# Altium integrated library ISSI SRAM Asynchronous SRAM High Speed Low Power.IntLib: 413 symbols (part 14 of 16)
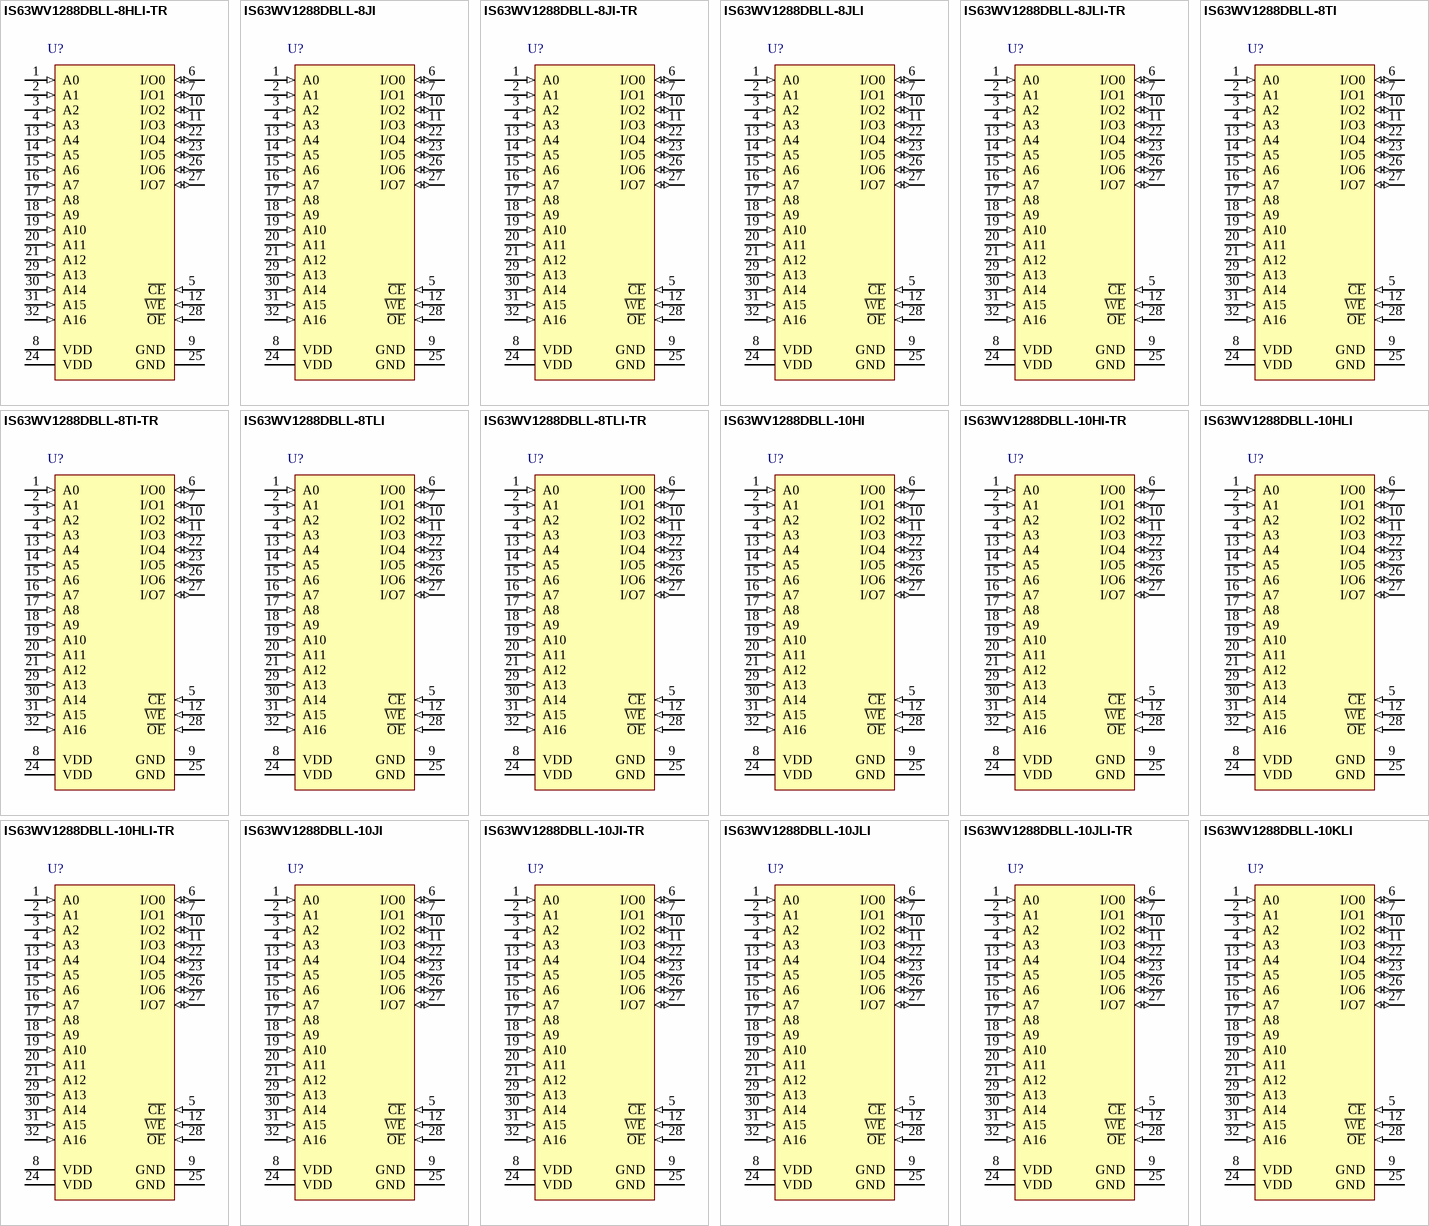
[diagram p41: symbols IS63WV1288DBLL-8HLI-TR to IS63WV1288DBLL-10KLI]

## IS63WV1288DBLL-8TI
designator U?
1 M High Speed CMOS SRAM, 128 K x 8, -40 to 85 degC, 32-Pin SOP (TSOP-2-32); Manufacturer: Integrated Silicon Solution Inc (ISSI); PartNumber: IS63WV1288DBLL-8TI; Organization: 128K x 8; Packing: Tray / Tube; Speed (ns): 8
footprint ISSI-TSOP-2-32_N (SOP, 32-Leads, Body 21.1x10.3mm, Pitch 1.27mm, IPC Medium Density)
pins: 1 A0 (in) "Address Inputs", 2 A1 (in) "Address Inputs", 3 A2 (in) "Address Inputs", 4 A3 (in) "Address Inputs", 5 ~{CE} (in) "Chip Enable Input", 6 I/O0 (io) "Bidirectional Ports", 7 I/O1 (io) "Bidirectional Ports", 8 VDD (power) "Power", 9 GND (power) "Ground", 10 I/O2 (io) "Bidirectional Ports", 11 I/O3 (io) "Bidirectional Ports", 12 ~{WE} (in) "Write Enable Input", 13 A4 (in) "Address Inputs", 14 A5 (in) "Address Inputs", 15 A6 (in) "Address Inputs", 16 A7 (in) "Address Inputs", 17 A8 (in) "Address Inputs", 18 A9 (in) "Address Inputs", 19 A10 (in) "Address Inputs", 20 A11 (in) "Address Inputs", 21 A12 (in) "Address Inputs", 22 I/O4 (io) "Bidirectional Ports", 23 I/O5 (io) "Bidirectional Ports", 24 VDD (power) "Power", 25 GND (power) "Ground", 26 I/O6 (io) "Bidirectional Ports", 27 I/O7 (io) "Bidirectional Ports", 28 ~{OE} (in) "Output Enable Input", 29 A13 (in) "Address Inputs", 30 A14 (in) "Address Inputs", 31 A15 (in) "Address Inputs", 32 A16 (in) "Address Inputs"

## IS63WV1288DBLL-8TI-TR
designator U?
1 M High Speed CMOS SRAM, 128 K x 8, -40 to 85 degC, 32-Pin SOP (TSOP-2-32); Manufacturer: Integrated Silicon Solution Inc (ISSI); PartNumber: IS63WV1288DBLL-8TI-TR; Organization: 128K x 8; Packing: Tape & Reel; Speed (ns): 8
footprint ISSI-TSOP-2-32_N (SOP, 32-Leads, Body 21.1x10.3mm, Pitch 1.27mm, IPC Medium Density)
pins: 1 A0 (in) "Address Inputs", 2 A1 (in) "Address Inputs", 3 A2 (in) "Address Inputs", 4 A3 (in) "Address Inputs", 5 ~{CE} (in) "Chip Enable Input", 6 I/O0 (io) "Bidirectional Ports", 7 I/O1 (io) "Bidirectional Ports", 8 VDD (power) "Power", 9 GND (power) "Ground", 10 I/O2 (io) "Bidirectional Ports", 11 I/O3 (io) "Bidirectional Ports", 12 ~{WE} (in) "Write Enable Input", 13 A4 (in) "Address Inputs", 14 A5 (in) "Address Inputs", 15 A6 (in) "Address Inputs", 16 A7 (in) "Address Inputs", 17 A8 (in) "Address Inputs", 18 A9 (in) "Address Inputs", 19 A10 (in) "Address Inputs", 20 A11 (in) "Address Inputs", 21 A12 (in) "Address Inputs", 22 I/O4 (io) "Bidirectional Ports", 23 I/O5 (io) "Bidirectional Ports", 24 VDD (power) "Power", 25 GND (power) "Ground", 26 I/O6 (io) "Bidirectional Ports", 27 I/O7 (io) "Bidirectional Ports", 28 ~{OE} (in) "Output Enable Input", 29 A13 (in) "Address Inputs", 30 A14 (in) "Address Inputs", 31 A15 (in) "Address Inputs", 32 A16 (in) "Address Inputs"

## IS63WV1288DBLL-8TLI
designator U?
1 M High Speed CMOS SRAM, 128 K x 8, -40 to 85 degC, 32-Pin SOP (TSOP-2-32), Pb-Free; Manufacturer: Integrated Silicon Solution Inc (ISSI); PartNumber: IS63WV1288DBLL-8TLI; Organization: 128K x 8; Packing: Tray / Tube; Speed (ns): 8
footprint ISSI-TSOP-2-32_N (SOP, 32-Leads, Body 21.1x10.3mm, Pitch 1.27mm, IPC Medium Density)
pins: 1 A0 (in) "Address Inputs", 2 A1 (in) "Address Inputs", 3 A2 (in) "Address Inputs", 4 A3 (in) "Address Inputs", 5 ~{CE} (in) "Chip Enable Input", 6 I/O0 (io) "Bidirectional Ports", 7 I/O1 (io) "Bidirectional Ports", 8 VDD (power) "Power", 9 GND (power) "Ground", 10 I/O2 (io) "Bidirectional Ports", 11 I/O3 (io) "Bidirectional Ports", 12 ~{WE} (in) "Write Enable Input", 13 A4 (in) "Address Inputs", 14 A5 (in) "Address Inputs", 15 A6 (in) "Address Inputs", 16 A7 (in) "Address Inputs", 17 A8 (in) "Address Inputs", 18 A9 (in) "Address Inputs", 19 A10 (in) "Address Inputs", 20 A11 (in) "Address Inputs", 21 A12 (in) "Address Inputs", 22 I/O4 (io) "Bidirectional Ports", 23 I/O5 (io) "Bidirectional Ports", 24 VDD (power) "Power", 25 GND (power) "Ground", 26 I/O6 (io) "Bidirectional Ports", 27 I/O7 (io) "Bidirectional Ports", 28 ~{OE} (in) "Output Enable Input", 29 A13 (in) "Address Inputs", 30 A14 (in) "Address Inputs", 31 A15 (in) "Address Inputs", 32 A16 (in) "Address Inputs"

## IS63WV1288DBLL-8TLI-TR
designator U?
1 M High Speed CMOS SRAM, 128 K x 8, -40 to 85 degC, 32-Pin SOP (TSOP-2-32), Pb-Free; Manufacturer: Integrated Silicon Solution Inc (ISSI); PartNumber: IS63WV1288DBLL-8TLI-TR; Organization: 128K x 8; Packing: Tape & Reel; Speed (ns): 8
footprint ISSI-TSOP-2-32_N (SOP, 32-Leads, Body 21.1x10.3mm, Pitch 1.27mm, IPC Medium Density)
pins: 1 A0 (in) "Address Inputs", 2 A1 (in) "Address Inputs", 3 A2 (in) "Address Inputs", 4 A3 (in) "Address Inputs", 5 ~{CE} (in) "Chip Enable Input", 6 I/O0 (io) "Bidirectional Ports", 7 I/O1 (io) "Bidirectional Ports", 8 VDD (power) "Power", 9 GND (power) "Ground", 10 I/O2 (io) "Bidirectional Ports", 11 I/O3 (io) "Bidirectional Ports", 12 ~{WE} (in) "Write Enable Input", 13 A4 (in) "Address Inputs", 14 A5 (in) "Address Inputs", 15 A6 (in) "Address Inputs", 16 A7 (in) "Address Inputs", 17 A8 (in) "Address Inputs", 18 A9 (in) "Address Inputs", 19 A10 (in) "Address Inputs", 20 A11 (in) "Address Inputs", 21 A12 (in) "Address Inputs", 22 I/O4 (io) "Bidirectional Ports", 23 I/O5 (io) "Bidirectional Ports", 24 VDD (power) "Power", 25 GND (power) "Ground", 26 I/O6 (io) "Bidirectional Ports", 27 I/O7 (io) "Bidirectional Ports", 28 ~{OE} (in) "Output Enable Input", 29 A13 (in) "Address Inputs", 30 A14 (in) "Address Inputs", 31 A15 (in) "Address Inputs", 32 A16 (in) "Address Inputs"

## IS63WV1288DBLL-10HI
designator U?
1 M High Speed CMOS SRAM, 128 K x 8, -40 to 85 degC, 32-Pin SOP (TSOP-1-32); Manufacturer: Integrated Silicon Solution Inc (ISSI); PartNumber: IS63WV1288DBLL-10HI; Organization: 128K x 8; Packing: Tray / Tube; Speed (ns): 10
footprint ISSI-TSOP-1-32-8000x13400DE_N (SOP, 32-Leads, Body 11.9x8.1mm, Pitch 0.5mm, IPC Medium Density)
pins: 1 A0 (in) "Address Input", 2 A1 (in) "Address Input", 3 A2 (in) "Address Input", 4 A3 (in) "Address Input", 5 ~{CE} (in) "Chip Enable Input", 6 I/O0 (io) "Bidirectional Port", 7 I/O1 (io) "Bidirectional Port", 8 VDD (power) "Power", 9 GND (power) "Ground", 10 I/O2 (io) "Bidirectional Port", 11 I/O3 (io) "Bidirectional Port", 12 ~{WE} (in) "Write Enable Input", 13 A4 (in) "Address Input", 14 A5 (in) "Address Input", 15 A6 (in) "Address Input", 16 A7 (in) "Address Input", 17 A8 (in) "Address Input", 18 A9 (in) "Address Input", 19 A10 (in) "Address Input", 20 A11 (in) "Address Input", 21 A12 (in) "Address Input", 22 I/O4 (io) "Bidirectional Port", 23 I/O5 (io) "Bidirectional Port", 24 VDD (power) "Power", 25 GND (power) "Ground", 26 I/O6 (io) "Bidirectional Port", 27 I/O7 (io) "Bidirectional Port", 28 ~{OE} (in) "Output Enable Input", 29 A13 (in) "Address Input", 30 A14 (in) "Address Input", 31 A15 (in) "Address Input", 32 A16 (in) "Address Input"

## IS63WV1288DBLL-10HI-TR
designator U?
1 M High Speed CMOS SRAM, 128 K x 8, -40 to 85 degC, 32-Pin SOP (TSOP-1-32); Manufacturer: Integrated Silicon Solution Inc (ISSI); PartNumber: IS63WV1288DBLL-10HI-TR; Organization: 128K x 8; Packing: Tape & Reel; Speed (ns): 10
footprint ISSI-TSOP-1-32-8000x13400DE_N (SOP, 32-Leads, Body 11.9x8.1mm, Pitch 0.5mm, IPC Medium Density)
pins: 1 A0 (in) "Address Input", 2 A1 (in) "Address Input", 3 A2 (in) "Address Input", 4 A3 (in) "Address Input", 5 ~{CE} (in) "Chip Enable Input", 6 I/O0 (io) "Bidirectional Port", 7 I/O1 (io) "Bidirectional Port", 8 VDD (power) "Power", 9 GND (power) "Ground", 10 I/O2 (io) "Bidirectional Port", 11 I/O3 (io) "Bidirectional Port", 12 ~{WE} (in) "Write Enable Input", 13 A4 (in) "Address Input", 14 A5 (in) "Address Input", 15 A6 (in) "Address Input", 16 A7 (in) "Address Input", 17 A8 (in) "Address Input", 18 A9 (in) "Address Input", 19 A10 (in) "Address Input", 20 A11 (in) "Address Input", 21 A12 (in) "Address Input", 22 I/O4 (io) "Bidirectional Port", 23 I/O5 (io) "Bidirectional Port", 24 VDD (power) "Power", 25 GND (power) "Ground", 26 I/O6 (io) "Bidirectional Port", 27 I/O7 (io) "Bidirectional Port", 28 ~{OE} (in) "Output Enable Input", 29 A13 (in) "Address Input", 30 A14 (in) "Address Input", 31 A15 (in) "Address Input", 32 A16 (in) "Address Input"

## IS63WV1288DBLL-10HLI
designator U?
1 M High Speed CMOS SRAM, 128 K x 8, -40 to 85 degC, 32-Pin SOP (TSOP-1-32), Pb-Free; Manufacturer: Integrated Silicon Solution Inc (ISSI); PartNumber: IS63WV1288DBLL-10HLI; Organization: 128K x 8; Packing: Tray / Tube; Speed (ns): 10
footprint ISSI-TSOP-1-32-8000x13400DE_N (SOP, 32-Leads, Body 11.9x8.1mm, Pitch 0.5mm, IPC Medium Density)
pins: 1 A0 (in) "Address Input", 2 A1 (in) "Address Input", 3 A2 (in) "Address Input", 4 A3 (in) "Address Input", 5 ~{CE} (in) "Chip Enable Input", 6 I/O0 (io) "Bidirectional Port", 7 I/O1 (io) "Bidirectional Port", 8 VDD (power) "Power", 9 GND (power) "Ground", 10 I/O2 (io) "Bidirectional Port", 11 I/O3 (io) "Bidirectional Port", 12 ~{WE} (in) "Write Enable Input", 13 A4 (in) "Address Input", 14 A5 (in) "Address Input", 15 A6 (in) "Address Input", 16 A7 (in) "Address Input", 17 A8 (in) "Address Input", 18 A9 (in) "Address Input", 19 A10 (in) "Address Input", 20 A11 (in) "Address Input", 21 A12 (in) "Address Input", 22 I/O4 (io) "Bidirectional Port", 23 I/O5 (io) "Bidirectional Port", 24 VDD (power) "Power", 25 GND (power) "Ground", 26 I/O6 (io) "Bidirectional Port", 27 I/O7 (io) "Bidirectional Port", 28 ~{OE} (in) "Output Enable Input", 29 A13 (in) "Address Input", 30 A14 (in) "Address Input", 31 A15 (in) "Address Input", 32 A16 (in) "Address Input"

## IS63WV1288DBLL-10HLI-TR
designator U?
1 M High Speed CMOS SRAM, 128 K x 8, -40 to 85 degC, 32-Pin SOP (TSOP-1-32), Pb-Free; Manufacturer: Integrated Silicon Solution Inc (ISSI); PartNumber: IS63WV1288DBLL-10HLI-TR; Organization: 128K x 8; Packing: Tape & Reel; Speed (ns): 10
footprint ISSI-TSOP-1-32-8000x13400DE_N (SOP, 32-Leads, Body 11.9x8.1mm, Pitch 0.5mm, IPC Medium Density)
pins: 1 A0 (in) "Address Input", 2 A1 (in) "Address Input", 3 A2 (in) "Address Input", 4 A3 (in) "Address Input", 5 ~{CE} (in) "Chip Enable Input", 6 I/O0 (io) "Bidirectional Port", 7 I/O1 (io) "Bidirectional Port", 8 VDD (power) "Power", 9 GND (power) "Ground", 10 I/O2 (io) "Bidirectional Port", 11 I/O3 (io) "Bidirectional Port", 12 ~{WE} (in) "Write Enable Input", 13 A4 (in) "Address Input", 14 A5 (in) "Address Input", 15 A6 (in) "Address Input", 16 A7 (in) "Address Input", 17 A8 (in) "Address Input", 18 A9 (in) "Address Input", 19 A10 (in) "Address Input", 20 A11 (in) "Address Input", 21 A12 (in) "Address Input", 22 I/O4 (io) "Bidirectional Port", 23 I/O5 (io) "Bidirectional Port", 24 VDD (power) "Power", 25 GND (power) "Ground", 26 I/O6 (io) "Bidirectional Port", 27 I/O7 (io) "Bidirectional Port", 28 ~{OE} (in) "Output Enable Input", 29 A13 (in) "Address Input", 30 A14 (in) "Address Input", 31 A15 (in) "Address Input", 32 A16 (in) "Address Input"

## IS63WV1288DBLL-10JI
designator U?
1 M High Speed CMOS SRAM, 128 K x 8, -40 to 85 degC, 32-Pin SOJ (SOJ-32_A); Manufacturer: Integrated Silicon Solution Inc (ISSI); PartNumber: IS63WV1288DBLL-10JI; Organization: 128K x 8; Packing: Tray / Tube; Speed (ns): 10
footprint ISSI-SOJ-32_A_N (SOJ, 32-Leads, Body 21.09x7.75mm, Pitch 1.27mm, IPC Medium Density)
pins: 1 A0 (in) "Address Input", 2 A1 (in) "Address Input", 3 A2 (in) "Address Input", 4 A3 (in) "Address Input", 5 ~{CE} (in) "Chip Enable Input", 6 I/O0 (io) "Bidirectional Port", 7 I/O1 (io) "Bidirectional Port", 8 VDD (power) "Power", 9 GND (power) "Ground", 10 I/O2 (io) "Bidirectional Port", 11 I/O3 (io) "Bidirectional Port", 12 ~{WE} (in) "Write Enable Input", 13 A4 (in) "Address Input", 14 A5 (in) "Address Input", 15 A6 (in) "Address Input", 16 A7 (in) "Address Input", 17 A8 (in) "Address Input", 18 A9 (in) "Address Input", 19 A10 (in) "Address Input", 20 A11 (in) "Address Input", 21 A12 (in) "Address Input", 22 I/O4 (io) "Bidirectional Port", 23 I/O5 (io) "Bidirectional Port", 24 VDD (power) "Power", 25 GND (power) "Ground", 26 I/O6 (io) "Bidirectional Port", 27 I/O7 (io) "Bidirectional Port", 28 ~{OE} (in) "Output Enable Input", 29 A13 (in) "Address Input", 30 A14 (in) "Address Input", 31 A15 (in) "Address Input", 32 A16 (in) "Address Input"

## IS63WV1288DBLL-10JI-TR
designator U?
1 M High Speed CMOS SRAM, 128 K x 8, -40 to 85 degC, 32-Pin SOJ (SOJ-32_A); Manufacturer: Integrated Silicon Solution Inc (ISSI); PartNumber: IS63WV1288DBLL-10JI-TR; Organization: 128K x 8; Packing: Tape & Reel; Speed (ns): 10
footprint ISSI-SOJ-32_A_N (SOJ, 32-Leads, Body 21.09x7.75mm, Pitch 1.27mm, IPC Medium Density)
pins: 1 A0 (in) "Address Input", 2 A1 (in) "Address Input", 3 A2 (in) "Address Input", 4 A3 (in) "Address Input", 5 ~{CE} (in) "Chip Enable Input", 6 I/O0 (io) "Bidirectional Port", 7 I/O1 (io) "Bidirectional Port", 8 VDD (power) "Power", 9 GND (power) "Ground", 10 I/O2 (io) "Bidirectional Port", 11 I/O3 (io) "Bidirectional Port", 12 ~{WE} (in) "Write Enable Input", 13 A4 (in) "Address Input", 14 A5 (in) "Address Input", 15 A6 (in) "Address Input", 16 A7 (in) "Address Input", 17 A8 (in) "Address Input", 18 A9 (in) "Address Input", 19 A10 (in) "Address Input", 20 A11 (in) "Address Input", 21 A12 (in) "Address Input", 22 I/O4 (io) "Bidirectional Port", 23 I/O5 (io) "Bidirectional Port", 24 VDD (power) "Power", 25 GND (power) "Ground", 26 I/O6 (io) "Bidirectional Port", 27 I/O7 (io) "Bidirectional Port", 28 ~{OE} (in) "Output Enable Input", 29 A13 (in) "Address Input", 30 A14 (in) "Address Input", 31 A15 (in) "Address Input", 32 A16 (in) "Address Input"

## IS63WV1288DBLL-10JLI
designator U?
1 M High Speed CMOS SRAM, 128 K x 8, -40 to 85 degC, 32-Pin SOJ (SOJ-32_A), Pb-Free; Manufacturer: Integrated Silicon Solution Inc (ISSI); PartNumber: IS63WV1288DBLL-10JLI; Organization: 128K x 8; Packing: Tray / Tube; Speed (ns): 10
footprint ISSI-SOJ-32_A_N (SOJ, 32-Leads, Body 21.09x7.75mm, Pitch 1.27mm, IPC Medium Density)
pins: 1 A0 (in) "Address Input", 2 A1 (in) "Address Input", 3 A2 (in) "Address Input", 4 A3 (in) "Address Input", 5 ~{CE} (in) "Chip Enable Input", 6 I/O0 (io) "Bidirectional Port", 7 I/O1 (io) "Bidirectional Port", 8 VDD (power) "Power", 9 GND (power) "Ground", 10 I/O2 (io) "Bidirectional Port", 11 I/O3 (io) "Bidirectional Port", 12 ~{WE} (in) "Write Enable Input", 13 A4 (in) "Address Input", 14 A5 (in) "Address Input", 15 A6 (in) "Address Input", 16 A7 (in) "Address Input", 17 A8 (in) "Address Input", 18 A9 (in) "Address Input", 19 A10 (in) "Address Input", 20 A11 (in) "Address Input", 21 A12 (in) "Address Input", 22 I/O4 (io) "Bidirectional Port", 23 I/O5 (io) "Bidirectional Port", 24 VDD (power) "Power", 25 GND (power) "Ground", 26 I/O6 (io) "Bidirectional Port", 27 I/O7 (io) "Bidirectional Port", 28 ~{OE} (in) "Output Enable Input", 29 A13 (in) "Address Input", 30 A14 (in) "Address Input", 31 A15 (in) "Address Input", 32 A16 (in) "Address Input"

## IS63WV1288DBLL-10JLI-TR
designator U?
1 M High Speed CMOS SRAM, 128 K x 8, -40 to 85 degC, 32-Pin SOJ (SOJ-32_A), Pb-Free; Manufacturer: Integrated Silicon Solution Inc (ISSI); PartNumber: IS63WV1288DBLL-10JLI-TR; Organization: 128K x 8; Packing: Tape & Reel; Speed (ns): 10
footprint ISSI-SOJ-32_A_N (SOJ, 32-Leads, Body 21.09x7.75mm, Pitch 1.27mm, IPC Medium Density)
pins: 1 A0 (in) "Address Input", 2 A1 (in) "Address Input", 3 A2 (in) "Address Input", 4 A3 (in) "Address Input", 5 ~{CE} (in) "Chip Enable Input", 6 I/O0 (io) "Bidirectional Port", 7 I/O1 (io) "Bidirectional Port", 8 VDD (power) "Power", 9 GND (power) "Ground", 10 I/O2 (io) "Bidirectional Port", 11 I/O3 (io) "Bidirectional Port", 12 ~{WE} (in) "Write Enable Input", 13 A4 (in) "Address Input", 14 A5 (in) "Address Input", 15 A6 (in) "Address Input", 16 A7 (in) "Address Input", 17 A8 (in) "Address Input", 18 A9 (in) "Address Input", 19 A10 (in) "Address Input", 20 A11 (in) "Address Input", 21 A12 (in) "Address Input", 22 I/O4 (io) "Bidirectional Port", 23 I/O5 (io) "Bidirectional Port", 24 VDD (power) "Power", 25 GND (power) "Ground", 26 I/O6 (io) "Bidirectional Port", 27 I/O7 (io) "Bidirectional Port", 28 ~{OE} (in) "Output Enable Input", 29 A13 (in) "Address Input", 30 A14 (in) "Address Input", 31 A15 (in) "Address Input", 32 A16 (in) "Address Input"

## IS63WV1288DBLL-10KLI
designator U?
1 M High Speed CMOS SRAM, 128 K x 8, -40 to 85 degC, 32-Pin SOJ (SOJ-32_B), Pb-Free; Manufacturer: Integrated Silicon Solution Inc (ISSI); PartNumber: IS63WV1288DBLL-10KLI; Organization: 128K x 8; Packing: Tray / Tube; Speed (ns): 10
footprint ISSI-SOJ-32_B_N (SOJ, 32-Leads, Body 21.08x10.29mm, Pitch 1.27mm, IPC Medium Density)
pins: 1 A0 (in) "Address Input", 2 A1 (in) "Address Input", 3 A2 (in) "Address Input", 4 A3 (in) "Address Input", 5 ~{CE} (in) "Chip Enable Input", 6 I/O0 (io) "Bidirectional Port", 7 I/O1 (io) "Bidirectional Port", 8 VDD (power) "Power", 9 GND (power) "Ground", 10 I/O2 (io) "Bidirectional Port", 11 I/O3 (io) "Bidirectional Port", 12 ~{WE} (in) "Write Enable Input", 13 A4 (in) "Address Input", 14 A5 (in) "Address Input", 15 A6 (in) "Address Input", 16 A7 (in) "Address Input", 17 A8 (in) "Address Input", 18 A9 (in) "Address Input", 19 A10 (in) "Address Input", 20 A11 (in) "Address Input", 21 A12 (in) "Address Input", 22 I/O4 (io) "Bidirectional Port", 23 I/O5 (io) "Bidirectional Port", 24 VDD (power) "Power", 25 GND (power) "Ground", 26 I/O6 (io) "Bidirectional Port", 27 I/O7 (io) "Bidirectional Port", 28 ~{OE} (in) "Output Enable Input", 29 A13 (in) "Address Input", 30 A14 (in) "Address Input", 31 A15 (in) "Address Input", 32 A16 (in) "Address Input"

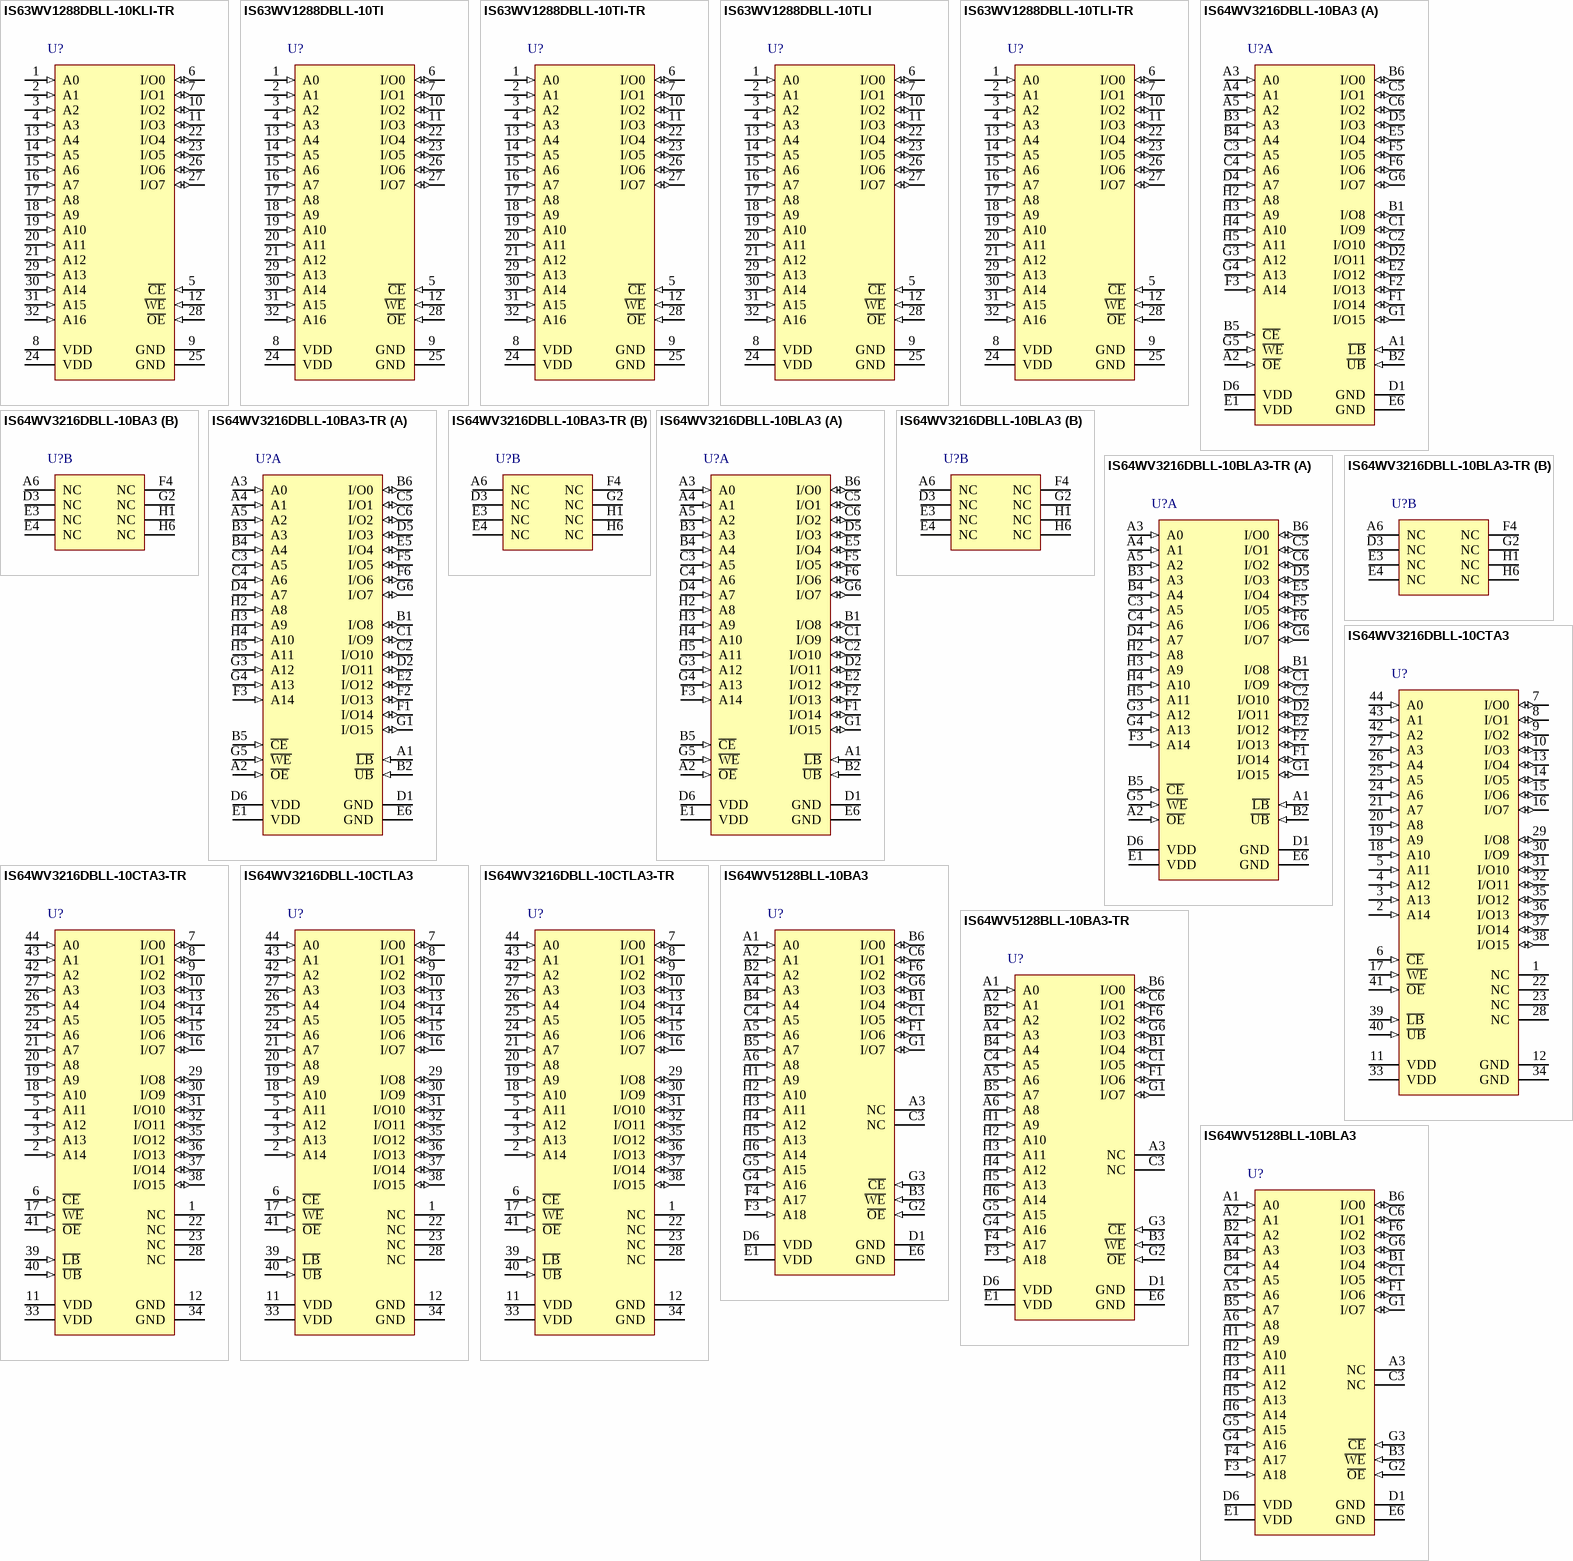
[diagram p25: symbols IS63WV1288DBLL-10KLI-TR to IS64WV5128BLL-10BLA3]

## IS63WV1288DBLL-10KLI-TR
designator U?
1 M High Speed CMOS SRAM, 128 K x 8, -40 to 85 degC, 32-Pin SOJ (SOJ-32_B), Pb-Free; Manufacturer: Integrated Silicon Solution Inc (ISSI); PartNumber: IS63WV1288DBLL-10KLI-TR; Organization: 128K x 8; Packing: Tape & Reel; Speed (ns): 10
footprint ISSI-SOJ-32_B_N (SOJ, 32-Leads, Body 21.08x10.29mm, Pitch 1.27mm, IPC Medium Density)
pins: 1 A0 (in) "Address Input", 2 A1 (in) "Address Input", 3 A2 (in) "Address Input", 4 A3 (in) "Address Input", 5 ~{CE} (in) "Chip Enable Input", 6 I/O0 (io) "Bidirectional Port", 7 I/O1 (io) "Bidirectional Port", 8 VDD (power) "Power", 9 GND (power) "Ground", 10 I/O2 (io) "Bidirectional Port", 11 I/O3 (io) "Bidirectional Port", 12 ~{WE} (in) "Write Enable Input", 13 A4 (in) "Address Input", 14 A5 (in) "Address Input", 15 A6 (in) "Address Input", 16 A7 (in) "Address Input", 17 A8 (in) "Address Input", 18 A9 (in) "Address Input", 19 A10 (in) "Address Input", 20 A11 (in) "Address Input", 21 A12 (in) "Address Input", 22 I/O4 (io) "Bidirectional Port", 23 I/O5 (io) "Bidirectional Port", 24 VDD (power) "Power", 25 GND (power) "Ground", 26 I/O6 (io) "Bidirectional Port", 27 I/O7 (io) "Bidirectional Port", 28 ~{OE} (in) "Output Enable Input", 29 A13 (in) "Address Input", 30 A14 (in) "Address Input", 31 A15 (in) "Address Input", 32 A16 (in) "Address Input"

## IS63WV1288DBLL-10TI
designator U?
1 M High Speed CMOS SRAM, 128 K x 8, -40 to 85 degC, 32-Pin SOP (TSOP-2-32); Manufacturer: Integrated Silicon Solution Inc (ISSI); PartNumber: IS63WV1288DBLL-10TI; Organization: 128K x 8; Packing: Tray / Tube; Speed (ns): 10
footprint ISSI-TSOP-2-32_N (SOP, 32-Leads, Body 21.1x10.3mm, Pitch 1.27mm, IPC Medium Density)
pins: 1 A0 (in) "Address Inputs", 2 A1 (in) "Address Inputs", 3 A2 (in) "Address Inputs", 4 A3 (in) "Address Inputs", 5 ~{CE} (in) "Chip Enable Input", 6 I/O0 (io) "Bidirectional Ports", 7 I/O1 (io) "Bidirectional Ports", 8 VDD (power) "Power", 9 GND (power) "Ground", 10 I/O2 (io) "Bidirectional Ports", 11 I/O3 (io) "Bidirectional Ports", 12 ~{WE} (in) "Write Enable Input", 13 A4 (in) "Address Inputs", 14 A5 (in) "Address Inputs", 15 A6 (in) "Address Inputs", 16 A7 (in) "Address Inputs", 17 A8 (in) "Address Inputs", 18 A9 (in) "Address Inputs", 19 A10 (in) "Address Inputs", 20 A11 (in) "Address Inputs", 21 A12 (in) "Address Inputs", 22 I/O4 (io) "Bidirectional Ports", 23 I/O5 (io) "Bidirectional Ports", 24 VDD (power) "Power", 25 GND (power) "Ground", 26 I/O6 (io) "Bidirectional Ports", 27 I/O7 (io) "Bidirectional Ports", 28 ~{OE} (in) "Output Enable Input", 29 A13 (in) "Address Inputs", 30 A14 (in) "Address Inputs", 31 A15 (in) "Address Inputs", 32 A16 (in) "Address Inputs"

## IS63WV1288DBLL-10TI-TR
designator U?
1 M High Speed CMOS SRAM, 128 K x 8, -40 to 85 degC, 32-Pin SOP (TSOP-2-32); Manufacturer: Integrated Silicon Solution Inc (ISSI); PartNumber: IS63WV1288DBLL-10TI-TR; Organization: 128K x 8; Packing: Tape & Reel; Speed (ns): 10
footprint ISSI-TSOP-2-32_N (SOP, 32-Leads, Body 21.1x10.3mm, Pitch 1.27mm, IPC Medium Density)
pins: 1 A0 (in) "Address Inputs", 2 A1 (in) "Address Inputs", 3 A2 (in) "Address Inputs", 4 A3 (in) "Address Inputs", 5 ~{CE} (in) "Chip Enable Input", 6 I/O0 (io) "Bidirectional Ports", 7 I/O1 (io) "Bidirectional Ports", 8 VDD (power) "Power", 9 GND (power) "Ground", 10 I/O2 (io) "Bidirectional Ports", 11 I/O3 (io) "Bidirectional Ports", 12 ~{WE} (in) "Write Enable Input", 13 A4 (in) "Address Inputs", 14 A5 (in) "Address Inputs", 15 A6 (in) "Address Inputs", 16 A7 (in) "Address Inputs", 17 A8 (in) "Address Inputs", 18 A9 (in) "Address Inputs", 19 A10 (in) "Address Inputs", 20 A11 (in) "Address Inputs", 21 A12 (in) "Address Inputs", 22 I/O4 (io) "Bidirectional Ports", 23 I/O5 (io) "Bidirectional Ports", 24 VDD (power) "Power", 25 GND (power) "Ground", 26 I/O6 (io) "Bidirectional Ports", 27 I/O7 (io) "Bidirectional Ports", 28 ~{OE} (in) "Output Enable Input", 29 A13 (in) "Address Inputs", 30 A14 (in) "Address Inputs", 31 A15 (in) "Address Inputs", 32 A16 (in) "Address Inputs"

## IS63WV1288DBLL-10TLI
designator U?
1 M High Speed CMOS SRAM, 128 K x 8, -40 to 85 degC, 32-Pin SOP (TSOP-2-32), Pb-Free; Manufacturer: Integrated Silicon Solution Inc (ISSI); PartNumber: IS63WV1288DBLL-10TLI; Organization: 128K x 8; Packing: Tray / Tube; Speed (ns): 10
footprint ISSI-TSOP-2-32_N (SOP, 32-Leads, Body 21.1x10.3mm, Pitch 1.27mm, IPC Medium Density)
pins: 1 A0 (in) "Address Inputs", 2 A1 (in) "Address Inputs", 3 A2 (in) "Address Inputs", 4 A3 (in) "Address Inputs", 5 ~{CE} (in) "Chip Enable Input", 6 I/O0 (io) "Bidirectional Ports", 7 I/O1 (io) "Bidirectional Ports", 8 VDD (power) "Power", 9 GND (power) "Ground", 10 I/O2 (io) "Bidirectional Ports", 11 I/O3 (io) "Bidirectional Ports", 12 ~{WE} (in) "Write Enable Input", 13 A4 (in) "Address Inputs", 14 A5 (in) "Address Inputs", 15 A6 (in) "Address Inputs", 16 A7 (in) "Address Inputs", 17 A8 (in) "Address Inputs", 18 A9 (in) "Address Inputs", 19 A10 (in) "Address Inputs", 20 A11 (in) "Address Inputs", 21 A12 (in) "Address Inputs", 22 I/O4 (io) "Bidirectional Ports", 23 I/O5 (io) "Bidirectional Ports", 24 VDD (power) "Power", 25 GND (power) "Ground", 26 I/O6 (io) "Bidirectional Ports", 27 I/O7 (io) "Bidirectional Ports", 28 ~{OE} (in) "Output Enable Input", 29 A13 (in) "Address Inputs", 30 A14 (in) "Address Inputs", 31 A15 (in) "Address Inputs", 32 A16 (in) "Address Inputs"

## IS63WV1288DBLL-10TLI-TR
designator U?
1 M High Speed CMOS SRAM, 128 K x 8, -40 to 85 degC, 32-Pin SOP (TSOP-2-32), Pb-Free; Manufacturer: Integrated Silicon Solution Inc (ISSI); PartNumber: IS63WV1288DBLL-10TLI-TR; Organization: 128K x 8; Packing: Tape & Reel; Speed (ns): 10
footprint ISSI-TSOP-2-32_N (SOP, 32-Leads, Body 21.1x10.3mm, Pitch 1.27mm, IPC Medium Density)
pins: 1 A0 (in) "Address Inputs", 2 A1 (in) "Address Inputs", 3 A2 (in) "Address Inputs", 4 A3 (in) "Address Inputs", 5 ~{CE} (in) "Chip Enable Input", 6 I/O0 (io) "Bidirectional Ports", 7 I/O1 (io) "Bidirectional Ports", 8 VDD (power) "Power", 9 GND (power) "Ground", 10 I/O2 (io) "Bidirectional Ports", 11 I/O3 (io) "Bidirectional Ports", 12 ~{WE} (in) "Write Enable Input", 13 A4 (in) "Address Inputs", 14 A5 (in) "Address Inputs", 15 A6 (in) "Address Inputs", 16 A7 (in) "Address Inputs", 17 A8 (in) "Address Inputs", 18 A9 (in) "Address Inputs", 19 A10 (in) "Address Inputs", 20 A11 (in) "Address Inputs", 21 A12 (in) "Address Inputs", 22 I/O4 (io) "Bidirectional Ports", 23 I/O5 (io) "Bidirectional Ports", 24 VDD (power) "Power", 25 GND (power) "Ground", 26 I/O6 (io) "Bidirectional Ports", 27 I/O7 (io) "Bidirectional Ports", 28 ~{OE} (in) "Output Enable Input", 29 A13 (in) "Address Inputs", 30 A14 (in) "Address Inputs", 31 A15 (in) "Address Inputs", 32 A16 (in) "Address Inputs"

## IS64WV3216DBLL-10BA3
designator U?
512 K High Speed Asynchronous CMOS SRAM, 32 K x 16, -40 to 125 degC, 48-Pin BGA (TF-BGA-48); Manufacturer: Integrated Silicon Solution Inc (ISSI); PartNumber: IS64WV3216DBLL-10BA3; Density: 512K; Organization: 32K x 16; Packing: Tray / Tube; Speed (ns): 10
footprint ISSI-TF-BGA-48-6000X8000DE (BGA, 48-Balls, Body 8x6mm, Pitch 0.75mm)
part A pins: A1 ~{LB} (in) "Lower-byte Control(I/O0-I/O7)", A2 ~{OE} (in) "Output Enable Input", A3 A0 (in) "Address Input", A4 A1 (in) "Address Input", A5 A2 (in) "Address Input", B1 I/O8 (io) "Data Input/Output", B2 ~{UB} (in) "Upper-byte Control(I/O8-I/O15)", B3 A3 (in) "Address Input", B4 A4 (in) "Address Input", B5 ~{CE} (in) "Chip Enable Input", B6 I/O0 (io) "Data Input/Output", C1 I/O9 (io) "Data Input/Output", C2 I/O10 (io) "Data Input/Output", C3 A5 (in) "Address Input", C4 A6 (in) "Address Input", C5 I/O1 (io) "Data Input/Output", C6 I/O2 (io) "Data Input/Output", D1 GND (power) "Ground", D2 I/O11 (io) "Data Input/Output", D4 A7 (in) "Address Input", D5 I/O3 (io) "Data Input/Output", D6 VDD (power) "Power", E1 VDD (power) "Power", E2 I/O12 (io) "Data Input/Output", E5 I/O4 (io) "Data Input/Output", E6 GND (power) "Ground", F1 I/O14 (io) "Data Input/Output", F2 I/O13 (io) "Data Input/Output", F3 A14 (in) "Address Input", F5 I/O5 (io) "Data Input/Output", F6 I/O6 (io) "Data Input/Output", G1 I/O15 (io) "Data Input/Output", G3 A12 (in) "Address Input", G4 A13 (in) "Address Input", G5 ~{WE} (in) "Write Enable Input", G6 I/O7 (io) "Data Input/Output", H2 A8 (in) "Address Input", H3 A9 (in) "Address Input", H4 A10 (in) "Address Input", H5 A11 (in) "Address Input"
part B pins: A6 NC "No Connection", D3 NC "No Connection", E3 NC "No Connection", E4 NC "No Connection", F4 NC "No Connection", G2 NC "No Connection", H1 NC "No Connection", H6 NC "No Connection"

## IS64WV3216DBLL-10BA3-TR
designator U?
512 K High Speed Asynchronous CMOS SRAM, 32 K x 16, -40 to 125 degC, 48-Pin BGA (TF-BGA-48); Manufacturer: Integrated Silicon Solution Inc (ISSI); PartNumber: IS64WV3216DBLL-10BA3-TR; Density: 512K; Organization: 32K x 16; Packing: Tape & Reel; Speed (ns): 10
footprint ISSI-TF-BGA-48-6000X8000DE (BGA, 48-Balls, Body 8x6mm, Pitch 0.75mm)
part A pins: A1 ~{LB} (in) "Lower-byte Control(I/O0-I/O7)", A2 ~{OE} (in) "Output Enable Input", A3 A0 (in) "Address Input", A4 A1 (in) "Address Input", A5 A2 (in) "Address Input", B1 I/O8 (io) "Data Input/Output", B2 ~{UB} (in) "Upper-byte Control(I/O8-I/O15)", B3 A3 (in) "Address Input", B4 A4 (in) "Address Input", B5 ~{CE} (in) "Chip Enable Input", B6 I/O0 (io) "Data Input/Output", C1 I/O9 (io) "Data Input/Output", C2 I/O10 (io) "Data Input/Output", C3 A5 (in) "Address Input", C4 A6 (in) "Address Input", C5 I/O1 (io) "Data Input/Output", C6 I/O2 (io) "Data Input/Output", D1 GND (power) "Ground", D2 I/O11 (io) "Data Input/Output", D4 A7 (in) "Address Input", D5 I/O3 (io) "Data Input/Output", D6 VDD (power) "Power", E1 VDD (power) "Power", E2 I/O12 (io) "Data Input/Output", E5 I/O4 (io) "Data Input/Output", E6 GND (power) "Ground", F1 I/O14 (io) "Data Input/Output", F2 I/O13 (io) "Data Input/Output", F3 A14 (in) "Address Input", F5 I/O5 (io) "Data Input/Output", F6 I/O6 (io) "Data Input/Output", G1 I/O15 (io) "Data Input/Output", G3 A12 (in) "Address Input", G4 A13 (in) "Address Input", G5 ~{WE} (in) "Write Enable Input", G6 I/O7 (io) "Data Input/Output", H2 A8 (in) "Address Input", H3 A9 (in) "Address Input", H4 A10 (in) "Address Input", H5 A11 (in) "Address Input"
part B pins: A6 NC "No Connection", D3 NC "No Connection", E3 NC "No Connection", E4 NC "No Connection", F4 NC "No Connection", G2 NC "No Connection", H1 NC "No Connection", H6 NC "No Connection"

## IS64WV3216DBLL-10BLA3
designator U?
512 K High Speed Asynchronous CMOS SRAM, 32 K x 16, -40 to 125 degC, 48-Pin BGA (TF-BGA-48), Pb-Free; Manufacturer: Integrated Silicon Solution Inc (ISSI); PartNumber: IS64WV3216DBLL-10BLA3; Density: 512K; Organization: 32K x 16; Packing: Tray / Tube; Speed (ns): 10
footprint ISSI-TF-BGA-48-6000X8000DE (BGA, 48-Balls, Body 8x6mm, Pitch 0.75mm)
part A pins: A1 ~{LB} (in) "Lower-byte Control(I/O0-I/O7)", A2 ~{OE} (in) "Output Enable Input", A3 A0 (in) "Address Input", A4 A1 (in) "Address Input", A5 A2 (in) "Address Input", B1 I/O8 (io) "Data Input/Output", B2 ~{UB} (in) "Upper-byte Control(I/O8-I/O15)", B3 A3 (in) "Address Input", B4 A4 (in) "Address Input", B5 ~{CE} (in) "Chip Enable Input", B6 I/O0 (io) "Data Input/Output", C1 I/O9 (io) "Data Input/Output", C2 I/O10 (io) "Data Input/Output", C3 A5 (in) "Address Input", C4 A6 (in) "Address Input", C5 I/O1 (io) "Data Input/Output", C6 I/O2 (io) "Data Input/Output", D1 GND (power) "Ground", D2 I/O11 (io) "Data Input/Output", D4 A7 (in) "Address Input", D5 I/O3 (io) "Data Input/Output", D6 VDD (power) "Power", E1 VDD (power) "Power", E2 I/O12 (io) "Data Input/Output", E5 I/O4 (io) "Data Input/Output", E6 GND (power) "Ground", F1 I/O14 (io) "Data Input/Output", F2 I/O13 (io) "Data Input/Output", F3 A14 (in) "Address Input", F5 I/O5 (io) "Data Input/Output", F6 I/O6 (io) "Data Input/Output", G1 I/O15 (io) "Data Input/Output", G3 A12 (in) "Address Input", G4 A13 (in) "Address Input", G5 ~{WE} (in) "Write Enable Input", G6 I/O7 (io) "Data Input/Output", H2 A8 (in) "Address Input", H3 A9 (in) "Address Input", H4 A10 (in) "Address Input", H5 A11 (in) "Address Input"
part B pins: A6 NC "No Connection", D3 NC "No Connection", E3 NC "No Connection", E4 NC "No Connection", F4 NC "No Connection", G2 NC "No Connection", H1 NC "No Connection", H6 NC "No Connection"

## IS64WV3216DBLL-10BLA3-TR
designator U?
512 K High Speed Asynchronous CMOS SRAM, 32 K x 16, -40 to 125 degC, 48-Pin BGA (TF-BGA-48), Pb-Free; Manufacturer: Integrated Silicon Solution Inc (ISSI); PartNumber: IS64WV3216DBLL-10BLA3-TR; Density: 512K; Organization: 32K x 16; Packing: Tape & Reel; Speed (ns): 10
footprint ISSI-TF-BGA-48-6000X8000DE (BGA, 48-Balls, Body 8x6mm, Pitch 0.75mm)
part A pins: A1 ~{LB} (in) "Lower-byte Control(I/O0-I/O7)", A2 ~{OE} (in) "Output Enable Input", A3 A0 (in) "Address Input", A4 A1 (in) "Address Input", A5 A2 (in) "Address Input", B1 I/O8 (io) "Data Input/Output", B2 ~{UB} (in) "Upper-byte Control(I/O8-I/O15)", B3 A3 (in) "Address Input", B4 A4 (in) "Address Input", B5 ~{CE} (in) "Chip Enable Input", B6 I/O0 (io) "Data Input/Output", C1 I/O9 (io) "Data Input/Output", C2 I/O10 (io) "Data Input/Output", C3 A5 (in) "Address Input", C4 A6 (in) "Address Input", C5 I/O1 (io) "Data Input/Output", C6 I/O2 (io) "Data Input/Output", D1 GND (power) "Ground", D2 I/O11 (io) "Data Input/Output", D4 A7 (in) "Address Input", D5 I/O3 (io) "Data Input/Output", D6 VDD (power) "Power", E1 VDD (power) "Power", E2 I/O12 (io) "Data Input/Output", E5 I/O4 (io) "Data Input/Output", E6 GND (power) "Ground", F1 I/O14 (io) "Data Input/Output", F2 I/O13 (io) "Data Input/Output", F3 A14 (in) "Address Input", F5 I/O5 (io) "Data Input/Output", F6 I/O6 (io) "Data Input/Output", G1 I/O15 (io) "Data Input/Output", G3 A12 (in) "Address Input", G4 A13 (in) "Address Input", G5 ~{WE} (in) "Write Enable Input", G6 I/O7 (io) "Data Input/Output", H2 A8 (in) "Address Input", H3 A9 (in) "Address Input", H4 A10 (in) "Address Input", H5 A11 (in) "Address Input"
part B pins: A6 NC "No Connection", D3 NC "No Connection", E3 NC "No Connection", E4 NC "No Connection", F4 NC "No Connection", G2 NC "No Connection", H1 NC "No Connection", H6 NC "No Connection"

## IS64WV3216DBLL-10CTA3
designator U?
512 K High Speed Asynchronous CMOS SRAM, 32 K x 16, -40 to 125 degC, 44-Pin SOP (TSOP-2-44); Manufacturer: Integrated Silicon Solution Inc (ISSI); PartNumber: IS64WV3216DBLL-10CTA3; Density: 512K; Organization: 32K x 16; Packing: Tray / Tube; Speed (ns): 10
footprint ISSI-TSOP-2-44_N (SOP, 44-Leads, Body 18.5x10.3mm, Pitch 0.8mm, IPC Medium Density)
pins: 1 NC "No Connection", 2 A14 (in) "Address Input", 3 A13 (in) "Address Input", 4 A12 (in) "Address Input", 5 A11 (in) "Address Input", 6 ~{CE} (in) "Chip Enable Input", 7 I/O0 (io) "Data Input/Output", 8 I/O1 (io) "Data Input/Output", 9 I/O2 (io) "Data Input/Output", 10 I/O3 (io) "Data Input/Output", 11 VDD (power) "Power", 12 GND (power) "Ground", 13 I/O4 (io) "Data Input/Output", 14 I/O5 (io) "Data Input/Output", 15 I/O6 (io) "Data Input/Output", 16 I/O7 (io) "Data Input/Output", 17 ~{WE} (in) "Write Enable Input", 18 A10 (in) "Address Input", 19 A9 (in) "Address Input", 20 A8 (in) "Address Input", 21 A7 (in) "Address Input", 22 NC "No Connection", 23 NC "No Connection", 24 A6 (in) "Address Input", 25 A5 (in) "Address Input", 26 A4 (in) "Address Input", 27 A3 (in) "Address Input", 28 NC "No Connection", 29 I/O8 (io) "Data Input/Output", 30 I/O9 (io) "Data Input/Output", 31 I/O10 (io) "Data Input/Output", 32 I/O11 (io) "Data Input/Output", 33 VDD (power) "Power", 34 GND (power) "Ground", 35 I/O12 (io) "Data Input/Output", 36 I/O13 (io) "Data Input/Output", 37 I/O14 (io) "Data Input/Output", 38 I/O15 (io) "Data Input/Output", 39 ~{LB} (in) "Lower-byte Control (I/O0-I/O7)", 40 ~{UB} (in) "Upper-byte Control (I/O8-I/O15)", 41 ~{OE} (in) "Output Enable Input", 42 A2 (in) "Address Input", 43 A1 (in) "Address Input", 44 A0 (in) "Address Input"

## IS64WV3216DBLL-10CTA3-TR
designator U?
512 K High Speed Asynchronous CMOS SRAM, 32 K x 16, -40 to 125 degC, 44-Pin SOP (TSOP-2-44); Manufacturer: Integrated Silicon Solution Inc (ISSI); PartNumber: IS64WV3216DBLL-10CTA3-TR; Density: 512K; Organization: 32K x 16; Packing: Tape & Reel; Speed (ns): 10
footprint ISSI-TSOP-2-44_N (SOP, 44-Leads, Body 18.5x10.3mm, Pitch 0.8mm, IPC Medium Density)
pins: 1 NC "No Connection", 2 A14 (in) "Address Input", 3 A13 (in) "Address Input", 4 A12 (in) "Address Input", 5 A11 (in) "Address Input", 6 ~{CE} (in) "Chip Enable Input", 7 I/O0 (io) "Data Input/Output", 8 I/O1 (io) "Data Input/Output", 9 I/O2 (io) "Data Input/Output", 10 I/O3 (io) "Data Input/Output", 11 VDD (power) "Power", 12 GND (power) "Ground", 13 I/O4 (io) "Data Input/Output", 14 I/O5 (io) "Data Input/Output", 15 I/O6 (io) "Data Input/Output", 16 I/O7 (io) "Data Input/Output", 17 ~{WE} (in) "Write Enable Input", 18 A10 (in) "Address Input", 19 A9 (in) "Address Input", 20 A8 (in) "Address Input", 21 A7 (in) "Address Input", 22 NC "No Connection", 23 NC "No Connection", 24 A6 (in) "Address Input", 25 A5 (in) "Address Input", 26 A4 (in) "Address Input", 27 A3 (in) "Address Input", 28 NC "No Connection", 29 I/O8 (io) "Data Input/Output", 30 I/O9 (io) "Data Input/Output", 31 I/O10 (io) "Data Input/Output", 32 I/O11 (io) "Data Input/Output", 33 VDD (power) "Power", 34 GND (power) "Ground", 35 I/O12 (io) "Data Input/Output", 36 I/O13 (io) "Data Input/Output", 37 I/O14 (io) "Data Input/Output", 38 I/O15 (io) "Data Input/Output", 39 ~{LB} (in) "Lower-byte Control (I/O0-I/O7)", 40 ~{UB} (in) "Upper-byte Control (I/O8-I/O15)", 41 ~{OE} (in) "Output Enable Input", 42 A2 (in) "Address Input", 43 A1 (in) "Address Input", 44 A0 (in) "Address Input"

## IS64WV3216DBLL-10CTLA3
designator U?
512 K High Speed Asynchronous CMOS SRAM, 32 K x 16, -40 to 125 degC, 44-Pin SOP (TSOP-2-44), Pb-Free; Manufacturer: Integrated Silicon Solution Inc (ISSI); PartNumber: IS64WV3216DBLL-10CTLA3; Density: 512K; Organization: 32K x 16; Packing: Tray / Tube; Speed (ns): 10
footprint ISSI-TSOP-2-44_N (SOP, 44-Leads, Body 18.5x10.3mm, Pitch 0.8mm, IPC Medium Density)
pins: 1 NC "No Connection", 2 A14 (in) "Address Input", 3 A13 (in) "Address Input", 4 A12 (in) "Address Input", 5 A11 (in) "Address Input", 6 ~{CE} (in) "Chip Enable Input", 7 I/O0 (io) "Data Input/Output", 8 I/O1 (io) "Data Input/Output", 9 I/O2 (io) "Data Input/Output", 10 I/O3 (io) "Data Input/Output", 11 VDD (power) "Power", 12 GND (power) "Ground", 13 I/O4 (io) "Data Input/Output", 14 I/O5 (io) "Data Input/Output", 15 I/O6 (io) "Data Input/Output", 16 I/O7 (io) "Data Input/Output", 17 ~{WE} (in) "Write Enable Input", 18 A10 (in) "Address Input", 19 A9 (in) "Address Input", 20 A8 (in) "Address Input", 21 A7 (in) "Address Input", 22 NC "No Connection", 23 NC "No Connection", 24 A6 (in) "Address Input", 25 A5 (in) "Address Input", 26 A4 (in) "Address Input", 27 A3 (in) "Address Input", 28 NC "No Connection", 29 I/O8 (io) "Data Input/Output", 30 I/O9 (io) "Data Input/Output", 31 I/O10 (io) "Data Input/Output", 32 I/O11 (io) "Data Input/Output", 33 VDD (power) "Power", 34 GND (power) "Ground", 35 I/O12 (io) "Data Input/Output", 36 I/O13 (io) "Data Input/Output", 37 I/O14 (io) "Data Input/Output", 38 I/O15 (io) "Data Input/Output", 39 ~{LB} (in) "Lower-byte Control (I/O0-I/O7)", 40 ~{UB} (in) "Upper-byte Control (I/O8-I/O15)", 41 ~{OE} (in) "Output Enable Input", 42 A2 (in) "Address Input", 43 A1 (in) "Address Input", 44 A0 (in) "Address Input"

## IS64WV3216DBLL-10CTLA3-TR
designator U?
512 K High Speed Asynchronous CMOS SRAM, 32 K x 16, -40 to 125 degC, 44-Pin SOP (TSOP-2-44), Pb-Free; Manufacturer: Integrated Silicon Solution Inc (ISSI); PartNumber: IS64WV3216DBLL-10CTLA3-TR; Density: 512K; Organization: 32K x 16; Packing: Tape & Reel; Speed (ns): 10
footprint ISSI-TSOP-2-44_N (SOP, 44-Leads, Body 18.5x10.3mm, Pitch 0.8mm, IPC Medium Density)
pins: 1 NC "No Connection", 2 A14 (in) "Address Input", 3 A13 (in) "Address Input", 4 A12 (in) "Address Input", 5 A11 (in) "Address Input", 6 ~{CE} (in) "Chip Enable Input", 7 I/O0 (io) "Data Input/Output", 8 I/O1 (io) "Data Input/Output", 9 I/O2 (io) "Data Input/Output", 10 I/O3 (io) "Data Input/Output", 11 VDD (power) "Power", 12 GND (power) "Ground", 13 I/O4 (io) "Data Input/Output", 14 I/O5 (io) "Data Input/Output", 15 I/O6 (io) "Data Input/Output", 16 I/O7 (io) "Data Input/Output", 17 ~{WE} (in) "Write Enable Input", 18 A10 (in) "Address Input", 19 A9 (in) "Address Input", 20 A8 (in) "Address Input", 21 A7 (in) "Address Input", 22 NC "No Connection", 23 NC "No Connection", 24 A6 (in) "Address Input", 25 A5 (in) "Address Input", 26 A4 (in) "Address Input", 27 A3 (in) "Address Input", 28 NC "No Connection", 29 I/O8 (io) "Data Input/Output", 30 I/O9 (io) "Data Input/Output", 31 I/O10 (io) "Data Input/Output", 32 I/O11 (io) "Data Input/Output", 33 VDD (power) "Power", 34 GND (power) "Ground", 35 I/O12 (io) "Data Input/Output", 36 I/O13 (io) "Data Input/Output", 37 I/O14 (io) "Data Input/Output", 38 I/O15 (io) "Data Input/Output", 39 ~{LB} (in) "Lower-byte Control (I/O0-I/O7)", 40 ~{UB} (in) "Upper-byte Control (I/O8-I/O15)", 41 ~{OE} (in) "Output Enable Input", 42 A2 (in) "Address Input", 43 A1 (in) "Address Input", 44 A0 (in) "Address Input"

## IS64WV5128BLL-10BA3
designator U?
4 M High Speed Asynchronous CMOS SRAM, 512 K x 8, -40 to 125 degC, 36-Pin BGA (TF-BGA-36); Manufacturer: Integrated Silicon Solution Inc (ISSI); PartNumber: IS64WV5128BLL-10BA3; Density: 4M; Organization: 512K x 8; Packing: Tray / Tube; Speed (ns): 10
footprint ISSI-TF-BGA-36-6000x8000DE (BGA, 36-Balls, Body 8x6mm, Pitch 0.75mm)
pins: A1 A0 (in) "Address Input", A2 A1 (in) "Address Input", A3 NC "No Connection", A4 A3 (in) "Address Input", A5 A6 (in) "Address Input", A6 A8 (in) "Address Input", B1 I/O4 (io) "Bidirectional Port", B2 A2 (in) "Address Input", B3 ~{WE} (in) "Write Enable Input", B4 A4 (in) "Address Input", B5 A7 (in) "Address Input", B6 I/O0 (io) "Bidirectional Port", C1 I/O5 (io) "Bidirectional Port", C3 NC "No Connection", C4 A5 (in) "Address Input", C6 I/O1 (io) "Bidirectional Port", D1 GND (power) "Ground", D6 VDD (power) "Power", E1 VDD (power) "Power", E6 GND (power) "Ground", F1 I/O6 (io) "Bidirectional Port", F3 A18 (in) "Address Input", F4 A17 (in) "Address Input", F6 I/O2 (io) "Bidirectional Port", G1 I/O7 (io) "Bidirectional Port", G2 ~{OE} (in) "Output Enable Input", G3 ~{CE} (in) "Chip Enable Input", G4 A16 (in) "Address Input", G5 A15 (in) "Address Input", G6 I/O3 (io) "Bidirectional Port", H1 A9 (in) "Address Input", H2 A10 (in) "Address Input", H3 A11 (in) "Address Input", H4 A12 (in) "Address Input", H5 A13 (in) "Address Input", H6 A14 (in) "Address Input"

## IS64WV5128BLL-10BA3-TR
designator U?
4 M High Speed Asynchronous CMOS SRAM, 512 K x 8, -40 to 125 degC, 36-Pin BGA (TF-BGA-36); Manufacturer: Integrated Silicon Solution Inc (ISSI); PartNumber: IS64WV5128BLL-10BA3-TR; Density: 4M; Organization: 512K x 8; Packing: Tape & Reel; Speed (ns): 10
footprint ISSI-TF-BGA-36-6000x8000DE (BGA, 36-Balls, Body 8x6mm, Pitch 0.75mm)
pins: A1 A0 (in) "Address Input", A2 A1 (in) "Address Input", A3 NC "No Connection", A4 A3 (in) "Address Input", A5 A6 (in) "Address Input", A6 A8 (in) "Address Input", B1 I/O4 (io) "Bidirectional Port", B2 A2 (in) "Address Input", B3 ~{WE} (in) "Write Enable Input", B4 A4 (in) "Address Input", B5 A7 (in) "Address Input", B6 I/O0 (io) "Bidirectional Port", C1 I/O5 (io) "Bidirectional Port", C3 NC "No Connection", C4 A5 (in) "Address Input", C6 I/O1 (io) "Bidirectional Port", D1 GND (power) "Ground", D6 VDD (power) "Power", E1 VDD (power) "Power", E6 GND (power) "Ground", F1 I/O6 (io) "Bidirectional Port", F3 A18 (in) "Address Input", F4 A17 (in) "Address Input", F6 I/O2 (io) "Bidirectional Port", G1 I/O7 (io) "Bidirectional Port", G2 ~{OE} (in) "Output Enable Input", G3 ~{CE} (in) "Chip Enable Input", G4 A16 (in) "Address Input", G5 A15 (in) "Address Input", G6 I/O3 (io) "Bidirectional Port", H1 A9 (in) "Address Input", H2 A10 (in) "Address Input", H3 A11 (in) "Address Input", H4 A12 (in) "Address Input", H5 A13 (in) "Address Input", H6 A14 (in) "Address Input"

## IS64WV5128BLL-10BLA3
designator U?
4 M High Speed Asynchronous CMOS SRAM, 512 K x 8, -40 to 125 degC, 36-Pin BGA (TF-BGA-36), Pb-Free; Manufacturer: Integrated Silicon Solution Inc (ISSI); PartNumber: IS64WV5128BLL-10BLA3; Density: 4M; Organization: 512K x 8; Packing: Tray / Tube; Speed (ns): 10
footprint ISSI-TF-BGA-36-6000x8000DE (BGA, 36-Balls, Body 8x6mm, Pitch 0.75mm)
pins: A1 A0 (in) "Address Input", A2 A1 (in) "Address Input", A3 NC "No Connection", A4 A3 (in) "Address Input", A5 A6 (in) "Address Input", A6 A8 (in) "Address Input", B1 I/O4 (io) "Bidirectional Port", B2 A2 (in) "Address Input", B3 ~{WE} (in) "Write Enable Input", B4 A4 (in) "Address Input", B5 A7 (in) "Address Input", B6 I/O0 (io) "Bidirectional Port", C1 I/O5 (io) "Bidirectional Port", C3 NC "No Connection", C4 A5 (in) "Address Input", C6 I/O1 (io) "Bidirectional Port", D1 GND (power) "Ground", D6 VDD (power) "Power", E1 VDD (power) "Power", E6 GND (power) "Ground", F1 I/O6 (io) "Bidirectional Port", F3 A18 (in) "Address Input", F4 A17 (in) "Address Input", F6 I/O2 (io) "Bidirectional Port", G1 I/O7 (io) "Bidirectional Port", G2 ~{OE} (in) "Output Enable Input", G3 ~{CE} (in) "Chip Enable Input", G4 A16 (in) "Address Input", G5 A15 (in) "Address Input", G6 I/O3 (io) "Bidirectional Port", H1 A9 (in) "Address Input", H2 A10 (in) "Address Input", H3 A11 (in) "Address Input", H4 A12 (in) "Address Input", H5 A13 (in) "Address Input", H6 A14 (in) "Address Input"

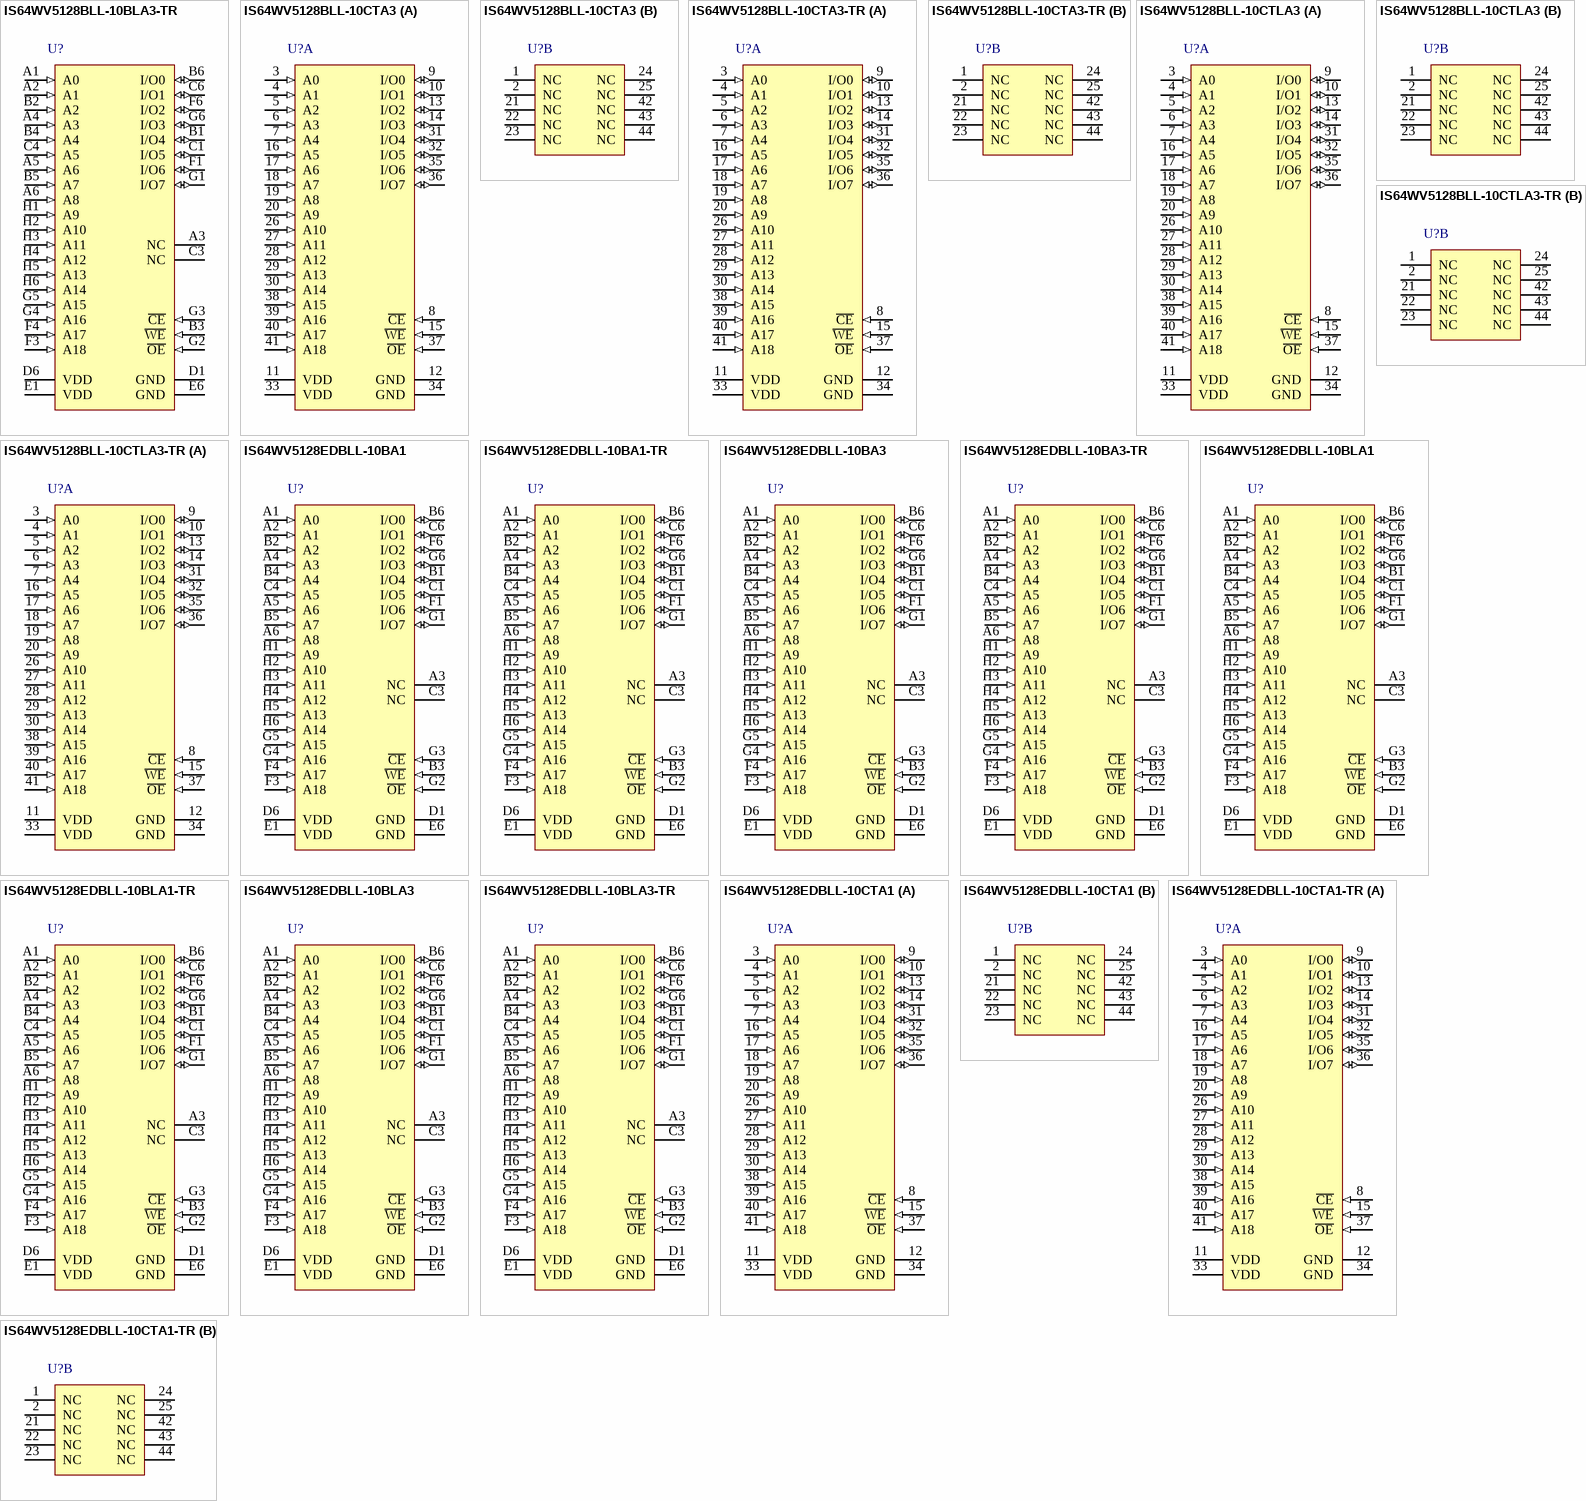
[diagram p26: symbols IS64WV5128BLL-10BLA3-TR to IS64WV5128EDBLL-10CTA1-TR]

## IS64WV5128BLL-10BLA3-TR
designator U?
4 M High Speed Asynchronous CMOS SRAM, 512 K x 8, -40 to 125 degC, 36-Pin BGA (TF-BGA-36), Pb-Free; Manufacturer: Integrated Silicon Solution Inc (ISSI); PartNumber: IS64WV5128BLL-10BLA3-TR; Density: 4M; Organization: 512K x 8; Packing: Tape & Reel; Speed (ns): 10
footprint ISSI-TF-BGA-36-6000x8000DE (BGA, 36-Balls, Body 8x6mm, Pitch 0.75mm)
pins: A1 A0 (in) "Address Input", A2 A1 (in) "Address Input", A3 NC "No Connection", A4 A3 (in) "Address Input", A5 A6 (in) "Address Input", A6 A8 (in) "Address Input", B1 I/O4 (io) "Bidirectional Port", B2 A2 (in) "Address Input", B3 ~{WE} (in) "Write Enable Input", B4 A4 (in) "Address Input", B5 A7 (in) "Address Input", B6 I/O0 (io) "Bidirectional Port", C1 I/O5 (io) "Bidirectional Port", C3 NC "No Connection", C4 A5 (in) "Address Input", C6 I/O1 (io) "Bidirectional Port", D1 GND (power) "Ground", D6 VDD (power) "Power", E1 VDD (power) "Power", E6 GND (power) "Ground", F1 I/O6 (io) "Bidirectional Port", F3 A18 (in) "Address Input", F4 A17 (in) "Address Input", F6 I/O2 (io) "Bidirectional Port", G1 I/O7 (io) "Bidirectional Port", G2 ~{OE} (in) "Output Enable Input", G3 ~{CE} (in) "Chip Enable Input", G4 A16 (in) "Address Input", G5 A15 (in) "Address Input", G6 I/O3 (io) "Bidirectional Port", H1 A9 (in) "Address Input", H2 A10 (in) "Address Input", H3 A11 (in) "Address Input", H4 A12 (in) "Address Input", H5 A13 (in) "Address Input", H6 A14 (in) "Address Input"

## IS64WV5128BLL-10CTA3
designator U?
4 M High Speed Asynchronous CMOS SRAM, 512 K x 8, -40 to 125 degC, 44-Pin SOP (TSOP-2-44); Manufacturer: Integrated Silicon Solution Inc (ISSI); PartNumber: IS64WV5128BLL-10CTA3; Density: 4M; Organization: 512K x 8; Packing: Tray / Tube; Speed (ns): 10
footprint ISSI-TSOP-2-44_N (SOP, 44-Leads, Body 18.5x10.3mm, Pitch 0.8mm, IPC Medium Density)
part A pins: 3 A0 (in) "Address Input", 4 A1 (in) "Address Input", 5 A2 (in) "Address Input", 6 A3 (in) "Address Input", 7 A4 (in) "Address Input", 8 ~{CE} (in) "Chip Enable Input", 9 I/O0 (io) "Bidirectional Port", 10 I/O1 (io) "Bidirectional Port", 11 VDD (power) "Power", 12 GND (power) "Ground", 13 I/O2 (io) "Bidirectional Port", 14 I/O3 (io) "Bidirectional Port", 15 ~{WE} (in) "Write Enable Input", 16 A5 (in) "Address Input", 17 A6 (in) "Address Input", 18 A7 (in) "Address Input", 19 A8 (in) "Address Input", 20 A9 (in) "Address Input", 26 A10 (in) "Address Input", 27 A11 (in) "Address Input", 28 A12 (in) "Address Input", 29 A13 (in) "Address Input", 30 A14 (in) "Address Input", 31 I/O4 (io) "Bidirectional Port", 32 I/O5 (io) "Bidirectional Port", 33 VDD (power) "Power", 34 GND (power) "Ground", 35 I/O6 (io) "Bidirectional Port", 36 I/O7 (io) "Bidirectional Port", 37 ~{OE} (in) "Output Enable Input", 38 A15 (in) "Address Input", 39 A16 (in) "Address Input", 40 A17 (in) "Address Input", 41 A18 (in) "Address Input"
part B pins: 1 NC "No Connection", 2 NC "No Connection", 21 NC "No Connection", 22 NC "No Connection", 23 NC "No Connection", 24 NC "No Connection", 25 NC "No Connection", 42 NC "No Connection", 43 NC "No Connection", 44 NC "No Connection"

## IS64WV5128BLL-10CTA3-TR
designator U?
4 M High Speed Asynchronous CMOS SRAM, 512 K x 8, -40 to 125 degC, 44-Pin SOP (TSOP-2-44); Manufacturer: Integrated Silicon Solution Inc (ISSI); PartNumber: IS64WV5128BLL-10CTA3-TR; Density: 4M; Organization: 512K x 8; Packing: Tape & Reel; Speed (ns): 10
footprint ISSI-TSOP-2-44_N (SOP, 44-Leads, Body 18.5x10.3mm, Pitch 0.8mm, IPC Medium Density)
part A pins: 3 A0 (in) "Address Input", 4 A1 (in) "Address Input", 5 A2 (in) "Address Input", 6 A3 (in) "Address Input", 7 A4 (in) "Address Input", 8 ~{CE} (in) "Chip Enable Input", 9 I/O0 (io) "Bidirectional Port", 10 I/O1 (io) "Bidirectional Port", 11 VDD (power) "Power", 12 GND (power) "Ground", 13 I/O2 (io) "Bidirectional Port", 14 I/O3 (io) "Bidirectional Port", 15 ~{WE} (in) "Write Enable Input", 16 A5 (in) "Address Input", 17 A6 (in) "Address Input", 18 A7 (in) "Address Input", 19 A8 (in) "Address Input", 20 A9 (in) "Address Input", 26 A10 (in) "Address Input", 27 A11 (in) "Address Input", 28 A12 (in) "Address Input", 29 A13 (in) "Address Input", 30 A14 (in) "Address Input", 31 I/O4 (io) "Bidirectional Port", 32 I/O5 (io) "Bidirectional Port", 33 VDD (power) "Power", 34 GND (power) "Ground", 35 I/O6 (io) "Bidirectional Port", 36 I/O7 (io) "Bidirectional Port", 37 ~{OE} (in) "Output Enable Input", 38 A15 (in) "Address Input", 39 A16 (in) "Address Input", 40 A17 (in) "Address Input", 41 A18 (in) "Address Input"
part B pins: 1 NC "No Connection", 2 NC "No Connection", 21 NC "No Connection", 22 NC "No Connection", 23 NC "No Connection", 24 NC "No Connection", 25 NC "No Connection", 42 NC "No Connection", 43 NC "No Connection", 44 NC "No Connection"

## IS64WV5128BLL-10CTLA3
designator U?
4 M High Speed Asynchronous CMOS SRAM, 512 K x 8, -40 to 125 degC, 44-Pin SOP (TSOP-2-44), Pb-Free; Manufacturer: Integrated Silicon Solution Inc (ISSI); PartNumber: IS64WV5128BLL-10CTLA3; Density: 4M; Organization: 512K x 8; Packing: Tray / Tube; Speed (ns): 10
footprint ISSI-TSOP-2-44_N (SOP, 44-Leads, Body 18.5x10.3mm, Pitch 0.8mm, IPC Medium Density)
part A pins: 3 A0 (in) "Address Input", 4 A1 (in) "Address Input", 5 A2 (in) "Address Input", 6 A3 (in) "Address Input", 7 A4 (in) "Address Input", 8 ~{CE} (in) "Chip Enable Input", 9 I/O0 (io) "Bidirectional Port", 10 I/O1 (io) "Bidirectional Port", 11 VDD (power) "Power", 12 GND (power) "Ground", 13 I/O2 (io) "Bidirectional Port", 14 I/O3 (io) "Bidirectional Port", 15 ~{WE} (in) "Write Enable Input", 16 A5 (in) "Address Input", 17 A6 (in) "Address Input", 18 A7 (in) "Address Input", 19 A8 (in) "Address Input", 20 A9 (in) "Address Input", 26 A10 (in) "Address Input", 27 A11 (in) "Address Input", 28 A12 (in) "Address Input", 29 A13 (in) "Address Input", 30 A14 (in) "Address Input", 31 I/O4 (io) "Bidirectional Port", 32 I/O5 (io) "Bidirectional Port", 33 VDD (power) "Power", 34 GND (power) "Ground", 35 I/O6 (io) "Bidirectional Port", 36 I/O7 (io) "Bidirectional Port", 37 ~{OE} (in) "Output Enable Input", 38 A15 (in) "Address Input", 39 A16 (in) "Address Input", 40 A17 (in) "Address Input", 41 A18 (in) "Address Input"
part B pins: 1 NC "No Connection", 2 NC "No Connection", 21 NC "No Connection", 22 NC "No Connection", 23 NC "No Connection", 24 NC "No Connection", 25 NC "No Connection", 42 NC "No Connection", 43 NC "No Connection", 44 NC "No Connection"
